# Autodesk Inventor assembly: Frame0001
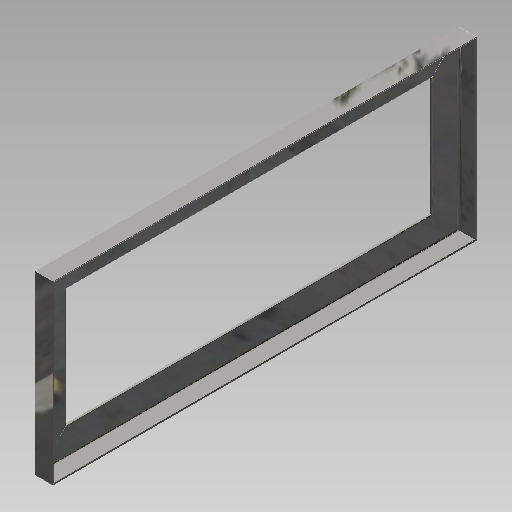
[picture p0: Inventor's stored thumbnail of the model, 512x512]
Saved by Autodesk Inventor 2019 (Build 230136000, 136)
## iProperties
Created: 2019-01
Part Number: Frame0001
Document SubType Name: Assembly
Designer: ElizabethC
_FrameDoc: Frame Assembly
_Version: 15.0.0
Author: ElizabethC
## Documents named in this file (10)
- N:\CARRUTHERS\Drawings\1946556 - Hirschvogel Platform\Assembly4\Frame\Frame0001.iam
- N:\CARRUTHERS\Drawings\1946556 - Hirschvogel Platform\Assembly4\Frame\Skeleton0001.ipt
- N:\CARRUTHERS\Drawings\1946556 - Hirschvogel Platform\Assembly4\Frame\ANSI L 5 x 3 x 5_16 00000001.ipt
- ANSI L 5 x 3 x 5_16 00000001.ipt
- N:\CARRUTHERS\Drawings\1946556 - Hirschvogel Platform\Assembly4\Frame\ANSI L 5 x 3 x 5_16 00000002.ipt
- ANSI L 5 x 3 x 5_16 00000002.ipt
- N:\CARRUTHERS\Drawings\1946556 - Hirschvogel Platform\Assembly4\Frame\ANSI L 5 x 3 x 5_16 00000003.ipt
- ANSI L 5 x 3 x 5_16 00000003.ipt
- N:\CARRUTHERS\Drawings\1946556 - Hirschvogel Platform\Assembly4\Frame\ANSI L 5 x 3 x 5_16 00000004.ipt
- ANSI L 5 x 3 x 5_16 00000004.ipt
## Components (5 placed, 5 different names)
1. Frame Reference Model
2. ANSI L 5 x 3 x 5_16 00000001:1
3. ANSI L 5 x 3 x 5_16 00000002:1
4. ANSI L 5 x 3 x 5_16 00000003:1
5. ANSI L 5 x 3 x 5_16 00000004:1
